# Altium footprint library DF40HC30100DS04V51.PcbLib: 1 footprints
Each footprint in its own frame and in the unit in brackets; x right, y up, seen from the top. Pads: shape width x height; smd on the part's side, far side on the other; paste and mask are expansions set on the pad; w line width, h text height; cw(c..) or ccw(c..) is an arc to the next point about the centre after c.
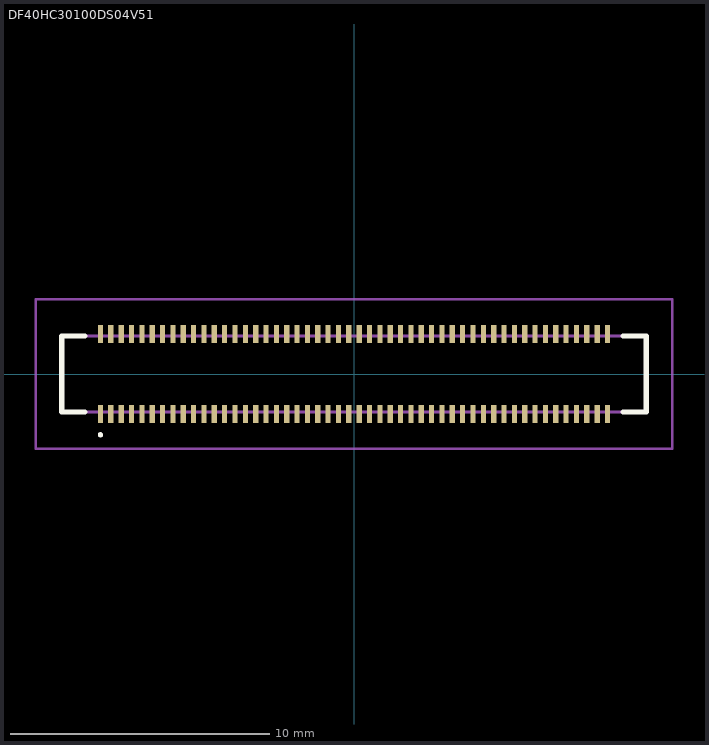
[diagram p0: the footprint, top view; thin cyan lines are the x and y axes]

## DF40HC30100DS04V51 [mm]
pads (100):
  rect 0.2x0.7 smd: 1(-9.8,-1.54) 2(-9.8,1.54) 3(-9.4,-1.54) 4(-9.4,1.54) 5(-9,-1.54) 6(-9,1.54) 7(-8.6,-1.54) 8(-8.6,1.54) 9(-8.2,-1.54) 10(-8.2,1.54) 11(-7.8,-1.54) 12(-7.8,1.54) 13(-7.4,-1.54) 14(-7.4,1.54) 15(-7,-1.54) 16(-7,1.54) 17(-6.6,-1.54) 18(-6.6,1.54) 19(-6.2,-1.54) 20(-6.2,1.54) 21(-5.8,-1.54) 22(-5.8,1.54) 23(-5.4,-1.54) 24(-5.4,1.54) 25(-5,-1.54) 26(-5,1.54) 27(-4.6,-1.54) 28(-4.6,1.54) 29(-4.2,-1.54) 30(-4.2,1.54) 31(-3.8,-1.54) 32(-3.8,1.54) 33(-3.4,-1.54) 34(-3.4,1.54) 35(-3,-1.54) 36(-3,1.54) 37(-2.6,-1.54) 38(-2.6,1.54) 39(-2.2,-1.54) 40(-2.2,1.54) 41(-1.8,-1.54) 42(-1.8,1.54) 43(-1.4,-1.54) 44(-1.4,1.54) 45(-1,-1.54) 46(-1,1.54) 47(-0.6,-1.54) 48(-0.6,1.54) 49(-0.2,-1.54) 50(-0.2,1.54) 51(0.2,-1.54) 52(0.2,1.54) 53(0.6,-1.54) 54(0.6,1.54) 55(1,-1.54) 56(1,1.54) 57(1.4,-1.54) 58(1.4,1.54) 59(1.8,-1.54) 60(1.8,1.54) 61(2.2,-1.54) 62(2.2,1.54) 63(2.6,-1.54) 64(2.6,1.54) 65(3,-1.54) 66(3,1.54) 67(3.4,-1.54) 68(3.4,1.54) 69(3.8,-1.54) 70(3.8,1.54) 71(4.2,-1.54) 72(4.2,1.54) 73(4.6,-1.54) 74(4.6,1.54) 75(5,-1.54) 76(5,1.54) 77(5.4,-1.54) 78(5.4,1.54) 79(5.8,-1.54) 80(5.8,1.54) 81(6.2,-1.54) 82(6.2,1.54) 83(6.6,-1.54) 84(6.6,1.54) 85(7,-1.54) 86(7,1.54) 87(7.4,-1.54) 88(7.4,1.54) 89(7.8,-1.54) 90(7.8,1.54) 91(8.2,-1.54) 92(8.2,1.54) 93(8.6,-1.54) 94(8.6,1.54) 95(9,-1.54) 96(9,1.54) 97(9.4,-1.54) 98(9.4,1.54) 99(9.8,-1.54) 100(9.8,1.54)
Top Overlay:
  lines w0.1: -9.8,-2.4 -9.8,-2.4 ; -9.8,-2.4 ccw(c-9.8,-2.35) -9.8,-2.3 ; -9.8,-2.4 cw(c-9.8,-2.35) -9.8,-2.3 ; -9.8,-2.3 -9.8,-2.3
  lines w0.2: -10.4,-1.47 -11.3,-1.47 -11.3,1.47 -10.4,1.47 ; 10.4,-1.47 11.3,-1.47 11.3,1.47 10.4,1.47
Mechanical 15:
  lines w0.1: -11.3,-1.47 11.3,-1.47 11.3,1.47 -11.3,1.47 -11.3,-1.47
Mechanical 20:
  lines w0.1: -12.3,-2.89 12.3,-2.89 12.3,2.89 -12.3,2.89 -12.3,-2.89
